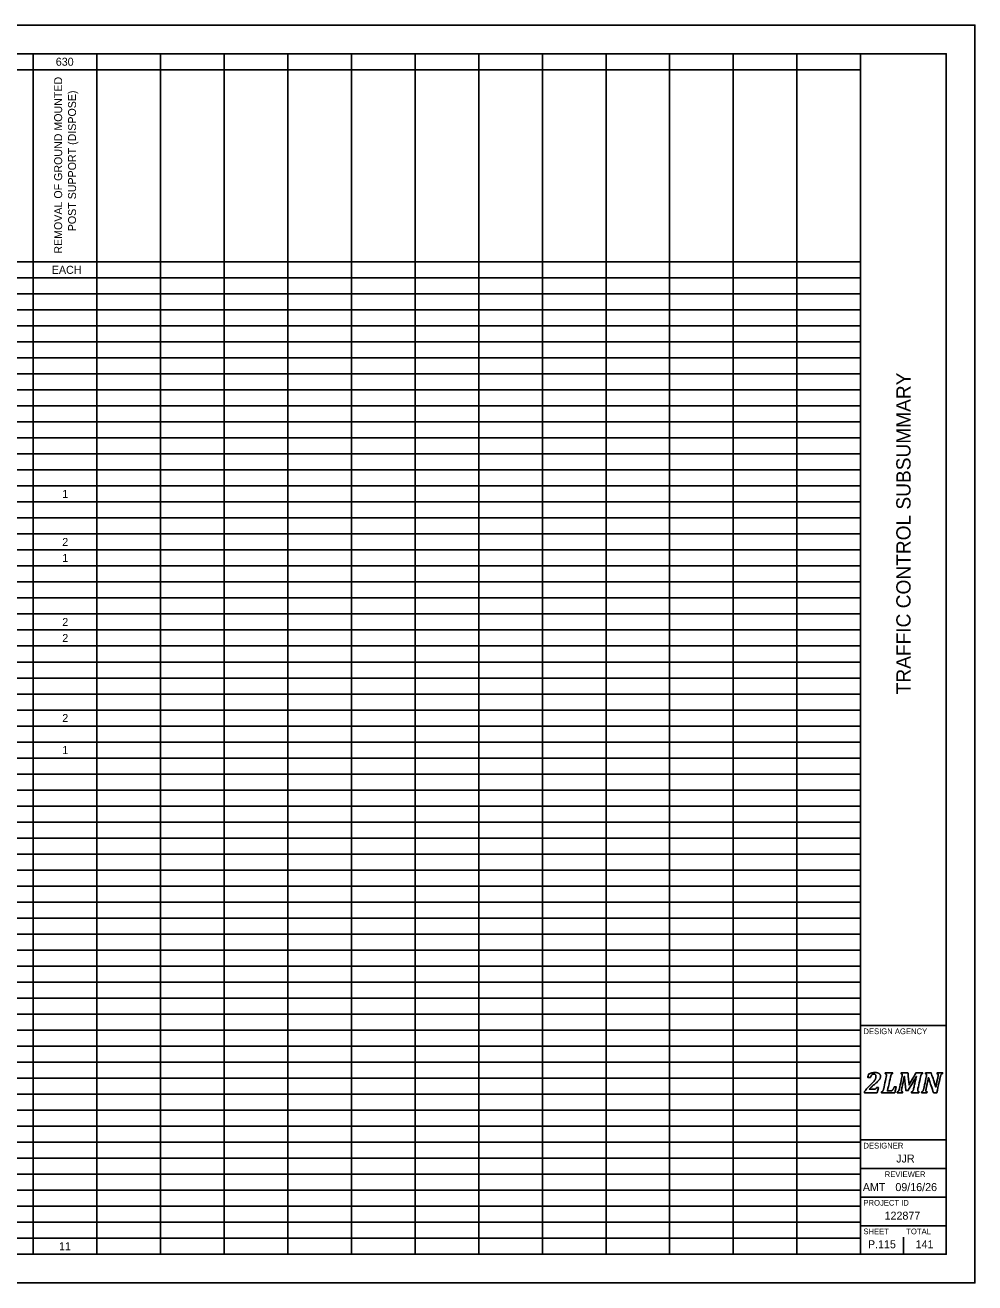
# Model space of a CAD drawing. Extents: x 0 to 34, y 0 to 22.
# Drawn here: x 17.38 to 34, y 0 to 22 of the extents above; entities that cross this region are included whole.
import ezdxf

# ---------------------------------------------------------------- set-up
doc = ezdxf.new("R2010")
doc.units = 0
for name, color, linetype in [('SH_Border', 7, 'Continuous'), ('SH_Cut_Line', 7, 'Continuous'), ('SH_Data', 7, 'Continuous'), ('SH_Text', 7, 'Continuous')]:
    doc.layers.add(name, color=color, linetype=linetype)

msp = doc.modelspace()

# ---------------------------------------------------------------- linework, layer by layer
at = {"layer": 'SH_Border'}
for p, q in [((32, 0.5), (32, 21.5)), ((32, 4.5), (33.5, 4.5)), ((32, 2.5), (33.5, 2.5)), ((32, 2), (33.5, 2)), ((32, 1.5), (33.5, 1.5)), ((32, 1), (33.5, 1))]:
    msp.add_line(p, q, dxfattribs=at)
msp.add_lwpolyline([(1.5, 21.5), (33.5, 21.5), (33.5, 0.5), (1.5, 0.5)], close=True, dxfattribs=at)
at = {"layer": 'SH_Cut_Line'}
msp.add_lwpolyline([(0, 0), (34, 0), (34, 22), (0, 22)], close=True, dxfattribs=at)
at = {"layer": 'SH_Data'}
for p, q in [((32.75, 3.5), (32.75, 3.5)), ((32.375, 0.675), (32.375, 0.675)), ((32.75, 0.5), (32.75, 0.8))]:
    msp.add_line(p, q, dxfattribs=at)
for points in [[(32.237, 3.388), (32.246, 3.388), (32.253, 3.389), (32.258, 3.39), (32.263, 3.392), (32.267, 3.394), (32.27, 3.397), (32.273, 3.401), (32.277, 3.408), (32.281, 3.417), (32.281, 3.417), (32.312, 3.417), (32.312, 3.417), (32.312, 3.417), (32.29, 3.326), (32.29, 3.326), (32.29, 3.326), (32.066, 3.326), (32.066, 3.326), (32.066, 3.326), (32.069, 3.343), (32.069, 3.343), (32.078, 3.358), (32.091, 3.375), (32.106, 3.394), (32.122, 3.412), (32.144, 3.435), (32.172, 3.462), (32.197, 3.486), (32.217, 3.506), (32.23, 3.521), (32.243, 3.537), (32.253, 3.551), (32.259, 3.566), (32.266, 3.58), (32.269, 3.595), (32.269, 3.61), (32.269, 3.622), (32.266, 3.632), (32.26, 3.64), (32.253, 3.647), (32.245, 3.65), (32.234, 3.65), (32.22, 3.65), (32.208, 3.646), (32.198, 3.636), (32.188, 3.627), (32.18, 3.613), (32.172, 3.593), (32.172, 3.593), (32.126, 3.593), (32.126, 3.593), (32.126, 3.593), (32.14, 3.654), (32.14, 3.654), (32.166, 3.663), (32.188, 3.669), (32.205, 3.673), (32.223, 3.676), (32.24, 3.678), (32.258, 3.678), (32.278, 3.678), (32.295, 3.675), (32.309, 3.669), (32.322, 3.664), (32.332, 3.656), (32.339, 3.646), (32.345, 3.637), (32.348, 3.626), (32.348, 3.613), (32.348, 3.602), (32.346, 3.591), (32.342, 3.581), (32.339, 3.571), (32.333, 3.56), (32.324, 3.549), (32.315, 3.539), (32.304, 3.526), (32.289, 3.513), (32.275, 3.499), (32.254, 3.482), (32.228, 3.46), (32.216, 3.45), (32.202, 3.438), (32.188, 3.425), (32.174, 3.412), (32.162, 3.4), (32.154, 3.391), (32.154, 3.391), (32.153, 3.388), (32.153, 3.388), (32.153, 3.388), (32.237, 3.388), (32.237, 3.388)], [(32.237, 3.388), (32.237, 3.388), (32.153, 3.388), (32.153, 3.388), (32.153, 3.388), (32.154, 3.391), (32.154, 3.391), (32.162, 3.4), (32.174, 3.412), (32.188, 3.425), (32.202, 3.438), (32.216, 3.45), (32.228, 3.46), (32.254, 3.482), (32.275, 3.499), (32.289, 3.513), (32.304, 3.526), (32.315, 3.539), (32.324, 3.549), (32.333, 3.56), (32.339, 3.571), (32.342, 3.581), (32.346, 3.591), (32.348, 3.602), (32.348, 3.613), (32.348, 3.626), (32.345, 3.637), (32.339, 3.646), (32.332, 3.656), (32.322, 3.664), (32.309, 3.669), (32.295, 3.675), (32.278, 3.678), (32.258, 3.678), (32.24, 3.678), (32.223, 3.676), (32.205, 3.673), (32.188, 3.669), (32.166, 3.663), (32.14, 3.654), (32.14, 3.654), (32.126, 3.593), (32.126, 3.593), (32.126, 3.593), (32.172, 3.593), (32.172, 3.593), (32.18, 3.613), (32.188, 3.627), (32.198, 3.636), (32.208, 3.646), (32.22, 3.65), (32.234, 3.65), (32.245, 3.65), (32.253, 3.647), (32.26, 3.64), (32.266, 3.632), (32.269, 3.622), (32.269, 3.61), (32.269, 3.595), (32.266, 3.58), (32.259, 3.566), (32.253, 3.551), (32.243, 3.537), (32.23, 3.521), (32.217, 3.506), (32.197, 3.486), (32.172, 3.462), (32.144, 3.435), (32.122, 3.412), (32.106, 3.394), (32.091, 3.375), (32.078, 3.358), (32.069, 3.343), (32.069, 3.343), (32.066, 3.326), (32.066, 3.326), (32.066, 3.326), (32.29, 3.326), (32.29, 3.326), (32.29, 3.326), (32.312, 3.417), (32.312, 3.417), (32.312, 3.417), (32.281, 3.417), (32.281, 3.417), (32.277, 3.408), (32.273, 3.401), (32.27, 3.397), (32.267, 3.394), (32.263, 3.392), (32.258, 3.39), (32.253, 3.389), (32.246, 3.388), (32.237, 3.388)], [(32.518, 3.356), (32.527, 3.356), (32.533, 3.357), (32.538, 3.358), (32.542, 3.36), (32.546, 3.362), (32.55, 3.365), (32.554, 3.368), (32.558, 3.372), (32.562, 3.377), (32.567, 3.382), (32.571, 3.388), (32.576, 3.397), (32.58, 3.405), (32.585, 3.415), (32.589, 3.427), (32.589, 3.427), (32.624, 3.427), (32.624, 3.427), (32.624, 3.427), (32.598, 3.326), (32.598, 3.326), (32.598, 3.326), (32.365, 3.326), (32.365, 3.326), (32.365, 3.326), (32.369, 3.343), (32.369, 3.343), (32.376, 3.345), (32.381, 3.348), (32.385, 3.351), (32.389, 3.355), (32.392, 3.36), (32.395, 3.366), (32.398, 3.373), (32.4, 3.382), (32.403, 3.395), (32.403, 3.395), (32.449, 3.605), (32.449, 3.605), (32.452, 3.615), (32.453, 3.625), (32.453, 3.635), (32.453, 3.642), (32.451, 3.647), (32.448, 3.651), (32.444, 3.654), (32.439, 3.656), (32.432, 3.657), (32.432, 3.657), (32.435, 3.674), (32.435, 3.674), (32.435, 3.674), (32.563, 3.674), (32.563, 3.674), (32.563, 3.674), (32.559, 3.657), (32.559, 3.657), (32.552, 3.655), (32.547, 3.652), (32.543, 3.649), (32.539, 3.645), (32.536, 3.64), (32.533, 3.634), (32.531, 3.627), (32.528, 3.618), (32.525, 3.605), (32.525, 3.605), (32.47, 3.356), (32.47, 3.356), (32.47, 3.356), (32.518, 3.356), (32.518, 3.356)], [(32.518, 3.356), (32.518, 3.356), (32.47, 3.356), (32.47, 3.356), (32.47, 3.356), (32.525, 3.605), (32.525, 3.605), (32.528, 3.618), (32.531, 3.627), (32.533, 3.634), (32.536, 3.64), (32.539, 3.645), (32.543, 3.649), (32.547, 3.652), (32.552, 3.655), (32.559, 3.657), (32.559, 3.657), (32.563, 3.674), (32.563, 3.674), (32.563, 3.674), (32.435, 3.674), (32.435, 3.674), (32.435, 3.674), (32.432, 3.657), (32.432, 3.657), (32.439, 3.656), (32.444, 3.654), (32.448, 3.651), (32.451, 3.647), (32.453, 3.642), (32.453, 3.635), (32.453, 3.625), (32.452, 3.615), (32.449, 3.605), (32.449, 3.605), (32.403, 3.395), (32.403, 3.395), (32.4, 3.382), (32.398, 3.373), (32.395, 3.366), (32.392, 3.36), (32.389, 3.355), (32.385, 3.351), (32.381, 3.348), (32.376, 3.345), (32.369, 3.343), (32.369, 3.343), (32.365, 3.326), (32.365, 3.326), (32.365, 3.326), (32.598, 3.326), (32.598, 3.326), (32.598, 3.326), (32.624, 3.427), (32.624, 3.427), (32.624, 3.427), (32.589, 3.427), (32.589, 3.427), (32.585, 3.415), (32.58, 3.405), (32.576, 3.397), (32.571, 3.388), (32.567, 3.382), (32.562, 3.377), (32.558, 3.372), (32.554, 3.368), (32.55, 3.365), (32.546, 3.362), (32.542, 3.36), (32.538, 3.358), (32.533, 3.357), (32.527, 3.356), (32.518, 3.356)], [(32.829, 3.674), (32.829, 3.674), (32.849, 3.461), (32.849, 3.461), (32.849, 3.461), (32.969, 3.674), (32.969, 3.674), (32.969, 3.674), (33.087, 3.674), (33.087, 3.674), (33.087, 3.674), (33.084, 3.657), (33.084, 3.657), (33.077, 3.655), (33.071, 3.652), (33.067, 3.649), (33.064, 3.645), (33.06, 3.64), (33.058, 3.634), (33.055, 3.627), (33.052, 3.618), (33.05, 3.605), (33.05, 3.605), (33.003, 3.395), (33.003, 3.395), (33.002, 3.39), (33.002, 3.387), (33.001, 3.384), (33.001, 3.382), (33.001, 3.379), (33, 3.376), (33, 3.373), (33, 3.369), (33, 3.365), (33, 3.358), (33.002, 3.353), (33.005, 3.349), (33.008, 3.346), (33.014, 3.344), (33.021, 3.343), (33.021, 3.343), (33.018, 3.326), (33.018, 3.326), (33.018, 3.326), (32.89, 3.326), (32.89, 3.326), (32.89, 3.326), (32.893, 3.343), (32.893, 3.343), (32.9, 3.345), (32.906, 3.348), (32.91, 3.351), (32.914, 3.355), (32.917, 3.36), (32.919, 3.366), (32.922, 3.373), (32.925, 3.382), (32.928, 3.395), (32.928, 3.395), (32.951, 3.502), (32.951, 3.502), (32.954, 3.513), (32.957, 3.529), (32.962, 3.548), (32.967, 3.568), (32.972, 3.588), (32.978, 3.609), (32.978, 3.609), (32.973, 3.609), (32.973, 3.609), (32.965, 3.594), (32.957, 3.579), (32.948, 3.563), (32.948, 3.563), (32.833, 3.364), (32.833, 3.364), (32.833, 3.364), (32.792, 3.364), (32.792, 3.364), (32.792, 3.364), (32.775, 3.518), (32.775, 3.518), (32.773, 3.537), (32.772, 3.554), (32.77, 3.569), (32.769, 3.583), (32.768, 3.597), (32.768, 3.611), (32.768, 3.611), (32.764, 3.611), (32.764, 3.611), (32.761, 3.596), (32.758, 3.578), (32.755, 3.558), (32.751, 3.538), (32.747, 3.521), (32.744, 3.507), (32.744, 3.507), (32.72, 3.395), (32.72, 3.395), (32.719, 3.39), (32.718, 3.387), (32.718, 3.384), (32.717, 3.382), (32.717, 3.379), (32.717, 3.376), (32.717, 3.373), (32.716, 3.369), (32.716, 3.365), (32.716, 3.358), (32.718, 3.353), (32.721, 3.349), (32.725, 3.346), (32.73, 3.344), (32.738, 3.343), (32.738, 3.343), (32.734, 3.326), (32.734, 3.326), (32.734, 3.326), (32.641, 3.326), (32.641, 3.326), (32.641, 3.326), (32.644, 3.343), (32.644, 3.343), (32.651, 3.345), (32.657, 3.348), (32.661, 3.351), (32.665, 3.355), (32.668, 3.36), (32.67, 3.366), (32.673, 3.373), (32.676, 3.382), (32.679, 3.395), (32.679, 3.395), (32.725, 3.605), (32.725, 3.605), (32.727, 3.615), (32.728, 3.625), (32.728, 3.635), (32.728, 3.642), (32.727, 3.647), (32.723, 3.651), (32.72, 3.654), (32.715, 3.656), (32.707, 3.657), (32.707, 3.657), (32.711, 3.674), (32.711, 3.674), (32.711, 3.674), (32.829, 3.674), (32.829, 3.674)], [(32.829, 3.674), (32.829, 3.674), (32.711, 3.674), (32.711, 3.674), (32.711, 3.674), (32.707, 3.657), (32.707, 3.657), (32.715, 3.656), (32.72, 3.654), (32.723, 3.651), (32.727, 3.647), (32.728, 3.642), (32.728, 3.635), (32.728, 3.625), (32.727, 3.615), (32.725, 3.605), (32.725, 3.605), (32.679, 3.395), (32.679, 3.395), (32.676, 3.382), (32.673, 3.373), (32.67, 3.366), (32.668, 3.36), (32.665, 3.355), (32.661, 3.351), (32.657, 3.348), (32.651, 3.345), (32.644, 3.343), (32.644, 3.343), (32.641, 3.326), (32.641, 3.326), (32.641, 3.326), (32.734, 3.326), (32.734, 3.326), (32.734, 3.326), (32.738, 3.343), (32.738, 3.343), (32.73, 3.344), (32.725, 3.346), (32.721, 3.349), (32.718, 3.353), (32.716, 3.358), (32.716, 3.365), (32.716, 3.369), (32.717, 3.373), (32.717, 3.376), (32.717, 3.379), (32.717, 3.382), (32.718, 3.384), (32.718, 3.387), (32.719, 3.39), (32.72, 3.395), (32.72, 3.395), (32.744, 3.507), (32.744, 3.507), (32.747, 3.521), (32.751, 3.538), (32.755, 3.558), (32.758, 3.578), (32.761, 3.596), (32.764, 3.611), (32.764, 3.611), (32.768, 3.611), (32.768, 3.611), (32.768, 3.597), (32.769, 3.583), (32.77, 3.569), (32.772, 3.554), (32.773, 3.537), (32.775, 3.518), (32.775, 3.518), (32.792, 3.364), (32.792, 3.364), (32.792, 3.364), (32.833, 3.364), (32.833, 3.364), (32.833, 3.364), (32.948, 3.563), (32.948, 3.563), (32.957, 3.579), (32.965, 3.594), (32.973, 3.609), (32.973, 3.609), (32.978, 3.609), (32.978, 3.609), (32.972, 3.588), (32.967, 3.568), (32.962, 3.548), (32.957, 3.529), (32.954, 3.513), (32.951, 3.502), (32.951, 3.502), (32.928, 3.395), (32.928, 3.395), (32.925, 3.382), (32.922, 3.373), (32.919, 3.366), (32.917, 3.36), (32.914, 3.355), (32.91, 3.351), (32.906, 3.348), (32.9, 3.345), (32.893, 3.343), (32.893, 3.343), (32.89, 3.326), (32.89, 3.326), (32.89, 3.326), (33.018, 3.326), (33.018, 3.326), (33.018, 3.326), (33.021, 3.343), (33.021, 3.343), (33.014, 3.344), (33.008, 3.346), (33.005, 3.349), (33.002, 3.353), (33, 3.358), (33, 3.365), (33, 3.369), (33, 3.373), (33, 3.376), (33.001, 3.379), (33.001, 3.382), (33.001, 3.384), (33.002, 3.387), (33.002, 3.39), (33.003, 3.395), (33.003, 3.395), (33.05, 3.605), (33.05, 3.605), (33.052, 3.618), (33.055, 3.627), (33.058, 3.634), (33.06, 3.64), (33.064, 3.645), (33.067, 3.649), (33.071, 3.652), (33.077, 3.655), (33.084, 3.657), (33.084, 3.657), (33.087, 3.674), (33.087, 3.674), (33.087, 3.674), (32.969, 3.674), (32.969, 3.674), (32.969, 3.674), (32.849, 3.461), (32.849, 3.461), (32.849, 3.461), (32.829, 3.674), (32.829, 3.674)], [(33.137, 3.674), (33.137, 3.674), (33.234, 3.674), (33.234, 3.674), (33.234, 3.674), (33.283, 3.53), (33.283, 3.53), (33.296, 3.49), (33.307, 3.456), (33.315, 3.426), (33.315, 3.426), (33.318, 3.426), (33.318, 3.426), (33.323, 3.455), (33.329, 3.488), (33.337, 3.523), (33.337, 3.523), (33.355, 3.605), (33.355, 3.605), (33.357, 3.615), (33.358, 3.625), (33.358, 3.635), (33.358, 3.642), (33.357, 3.647), (33.353, 3.651), (33.35, 3.654), (33.345, 3.656), (33.337, 3.657), (33.337, 3.657), (33.341, 3.674), (33.341, 3.674), (33.341, 3.674), (33.434, 3.674), (33.434, 3.674), (33.434, 3.674), (33.431, 3.657), (33.431, 3.657), (33.424, 3.655), (33.418, 3.652), (33.414, 3.649), (33.41, 3.645), (33.407, 3.64), (33.405, 3.634), (33.402, 3.627), (33.399, 3.618), (33.396, 3.605), (33.396, 3.605), (33.335, 3.326), (33.335, 3.326), (33.335, 3.326), (33.277, 3.326), (33.277, 3.326), (33.277, 3.326), (33.216, 3.504), (33.216, 3.504), (33.211, 3.518), (33.207, 3.531), (33.204, 3.543), (33.2, 3.556), (33.195, 3.571), (33.19, 3.59), (33.19, 3.59), (33.186, 3.59), (33.186, 3.59), (33.185, 3.579), (33.182, 3.563), (33.179, 3.543), (33.175, 3.523), (33.17, 3.501), (33.165, 3.478), (33.165, 3.478), (33.147, 3.395), (33.147, 3.395), (33.146, 3.39), (33.145, 3.387), (33.145, 3.384), (33.144, 3.382), (33.144, 3.379), (33.144, 3.376), (33.143, 3.373), (33.143, 3.369), (33.143, 3.365), (33.143, 3.358), (33.145, 3.353), (33.148, 3.349), (33.152, 3.346), (33.157, 3.344), (33.164, 3.343), (33.164, 3.343), (33.161, 3.326), (33.161, 3.326), (33.161, 3.326), (33.067, 3.326), (33.067, 3.326), (33.067, 3.326), (33.071, 3.343), (33.071, 3.343), (33.078, 3.345), (33.083, 3.348), (33.087, 3.351), (33.091, 3.355), (33.094, 3.36), (33.097, 3.366), (33.1, 3.373), (33.102, 3.382), (33.105, 3.395), (33.105, 3.395), (33.151, 3.605), (33.151, 3.605), (33.154, 3.615), (33.155, 3.625), (33.155, 3.635), (33.155, 3.642), (33.153, 3.647), (33.15, 3.651), (33.146, 3.654), (33.141, 3.656), (33.134, 3.657), (33.134, 3.657), (33.137, 3.674), (33.137, 3.674)], [(33.137, 3.674), (33.137, 3.674), (33.134, 3.657), (33.134, 3.657), (33.141, 3.656), (33.146, 3.654), (33.15, 3.651), (33.153, 3.647), (33.155, 3.642), (33.155, 3.635), (33.155, 3.625), (33.154, 3.615), (33.151, 3.605), (33.151, 3.605), (33.105, 3.395), (33.105, 3.395), (33.102, 3.382), (33.1, 3.373), (33.097, 3.366), (33.094, 3.36), (33.091, 3.355), (33.087, 3.351), (33.083, 3.348), (33.078, 3.345), (33.071, 3.343), (33.071, 3.343), (33.067, 3.326), (33.067, 3.326), (33.067, 3.326), (33.161, 3.326), (33.161, 3.326), (33.161, 3.326), (33.164, 3.343), (33.164, 3.343), (33.157, 3.344), (33.152, 3.346), (33.148, 3.349), (33.145, 3.353), (33.143, 3.358), (33.143, 3.365), (33.143, 3.369), (33.143, 3.373), (33.144, 3.376), (33.144, 3.379), (33.144, 3.382), (33.145, 3.384), (33.145, 3.387), (33.146, 3.39), (33.147, 3.395), (33.147, 3.395), (33.165, 3.478), (33.165, 3.478), (33.17, 3.501), (33.175, 3.523), (33.179, 3.543), (33.182, 3.563), (33.185, 3.579), (33.186, 3.59), (33.186, 3.59), (33.19, 3.59), (33.19, 3.59), (33.195, 3.571), (33.2, 3.556), (33.204, 3.543), (33.207, 3.531), (33.211, 3.518), (33.216, 3.504), (33.216, 3.504), (33.277, 3.326), (33.277, 3.326), (33.277, 3.326), (33.335, 3.326), (33.335, 3.326), (33.335, 3.326), (33.396, 3.605), (33.396, 3.605), (33.399, 3.618), (33.402, 3.627), (33.405, 3.634), (33.407, 3.64), (33.41, 3.645), (33.414, 3.649), (33.418, 3.652), (33.424, 3.655), (33.431, 3.657), (33.431, 3.657), (33.434, 3.674), (33.434, 3.674), (33.434, 3.674), (33.341, 3.674), (33.341, 3.674), (33.341, 3.674), (33.337, 3.657), (33.337, 3.657), (33.345, 3.656), (33.35, 3.654), (33.353, 3.651), (33.357, 3.647), (33.358, 3.642), (33.358, 3.635), (33.358, 3.625), (33.357, 3.615), (33.355, 3.605), (33.355, 3.605), (33.337, 3.523), (33.337, 3.523), (33.329, 3.488), (33.323, 3.455), (33.318, 3.426), (33.318, 3.426), (33.315, 3.426), (33.315, 3.426), (33.307, 3.456), (33.296, 3.49), (33.283, 3.53), (33.283, 3.53), (33.234, 3.674), (33.234, 3.674), (33.234, 3.674), (33.137, 3.674), (33.137, 3.674)]]:
    msp.add_open_spline(points, degree=3, dxfattribs=at)
at = {"layer": 'SH_Text'}
for p, q in [((1.5, 21.5), (32, 21.5)), ((17.52, 21.5), (17.52, 0.5)), ((18.634, 21.5), (18.634, 0.5)), ((19.748, 21.5), (19.748, 0.5)), ((20.861, 21.5), (20.861, 0.5)), ((21.975, 21.5), (21.975, 0.5)), ((23.089, 21.5), (23.089, 0.5)), ((24.203, 21.5), (24.203, 0.5)), ((25.317, 21.5), (25.317, 0.5)), ((26.431, 21.5), (26.431, 0.5)), ((27.545, 21.5), (27.545, 0.5)), ((28.658, 21.5), (28.658, 0.5)), ((29.772, 21.5), (29.772, 0.5)), ((30.886, 21.5), (30.886, 0.5)), ((32, 21.5), (32, 0.5)), ((10.673, 21.22), (32, 21.22)), ((10.673, 17.86), (32, 17.86)), ((1.5, 17.58), (32, 17.58)), ((1.5, 17.3), (32, 17.3)), ((1.5, 17.02), (32, 17.02)), ((1.5, 16.74), (32, 16.74)), ((1.5, 16.46), (32, 16.46)), ((1.5, 16.18), (32, 16.18)), ((1.5, 15.9), (32, 15.9)), ((1.5, 15.62), (32, 15.62)), ((1.5, 15.34), (32, 15.34)), ((1.5, 15.06), (32, 15.06)), ((1.5, 14.78), (32, 14.78)), ((1.5, 14.5), (32, 14.5)), ((1.5, 14.22), (32, 14.22)), ((1.5, 13.94), (32, 13.94)), ((1.5, 13.66), (32, 13.66)), ((1.5, 13.38), (32, 13.38)), ((1.5, 13.1), (32, 13.1)), ((1.5, 12.82), (32, 12.82)), ((1.5, 12.54), (32, 12.54)), ((1.5, 12.26), (32, 12.26)), ((1.5, 11.98), (32, 11.98)), ((1.5, 11.7), (32, 11.7)), ((1.5, 11.42), (32, 11.42)), ((1.5, 11.14), (32, 11.14)), ((1.5, 10.86), (32, 10.86)), ((1.5, 10.58), (32, 10.58)), ((1.5, 10.3), (32, 10.3)), ((1.5, 10.02), (32, 10.02)), ((1.5, 9.74), (32, 9.74)), ((1.5, 9.46), (32, 9.46)), ((1.5, 9.18), (32, 9.18)), ((1.5, 8.9), (32, 8.9)), ((1.5, 8.62), (32, 8.62)), ((1.5, 8.34), (32, 8.34)), ((1.5, 8.06), (32, 8.06)), ((1.5, 7.78), (32, 7.78)), ((1.5, 7.5), (32, 7.5)), ((1.5, 7.22), (32, 7.22)), ((1.5, 6.94), (32, 6.94)), ((1.5, 6.66), (32, 6.66)), ((1.5, 6.38), (32, 6.38)), ((1.5, 6.1), (32, 6.1)), ((1.5, 5.82), (32, 5.82)), ((1.5, 5.54), (32, 5.54)), ((1.5, 5.26), (32, 5.26)), ((1.5, 4.98), (32, 4.98)), ((1.5, 4.7), (32, 4.7)), ((1.5, 4.42), (32, 4.42)), ((1.5, 4.14), (32, 4.14)), ((1.5, 3.86), (32, 3.86)), ((1.5, 3.58), (32, 3.58)), ((1.5, 3.3), (32, 3.3)), ((1.5, 3.02), (32, 3.02)), ((1.5, 2.74), (32, 2.74)), ((1.5, 2.46), (32, 2.46)), ((1.5, 2.18), (32, 2.18)), ((1.5, 1.9), (32, 1.9)), ((1.5, 1.62), (32, 1.62)), ((1.5, 1.34), (32, 1.34)), ((1.5, 1.06), (32, 1.06)), ((1.5, 0.78), (32, 0.78)), ((1.5, 0.5), (32, 0.5))]:
    msp.add_line(p, q, dxfattribs=at)

# ---------------------------------------------------------------- texts
at = {"layer": 'SH_Data'}
msp.add_text('TRAFFIC CONTROL SUBSUMMARY', height=0.25, rotation=90, dxfattribs=at).set_placement((32.875, 10.295))
for s, height, p in [('DESIGN AGENCY', 0.1, (32.05, 4.35)), ('DESIGNER', 0.1, (32.05, 2.35)), ('JJR', 0.14, (32.624, 2.105)), ('REVIEWER', 0.1, (32.422, 1.85)), ('AMT', 0.14, (32.039, 1.605)), ('09/16/26', 0.14, (32.609, 1.605)), ('PROJECT ID', 0.1, (32.05, 1.35)), ('122877', 0.14, (32.42, 1.105)), ('SHEET', 0.1, (32.05, 0.85)), ('TOTAL', 0.1, (32.8, 0.85)), ('P.115', 0.14, (32.129, 0.605)), ('141', 0.14, (32.963, 0.605))]:
    msp.add_text(s, height=height, dxfattribs=at).set_placement(p)
at = {"layer": 'SH_Text'}
for s, p in [('630', (17.914, 21.29)), ('EACH', (17.844, 17.65)), ('1', (18.027, 13.73)), ('2', (18.027, 12.89)), ('1', (18.027, 12.61)), ('2', (18.027, 11.49)), ('2', (18.027, 11.21)), ('2', (18.027, 9.81)), ('1', (18.027, 9.25)), ('11', (17.971, 0.57))]:
    msp.add_text(s, height=0.14, dxfattribs=at).set_placement(p)
for s, p in [('REMOVAL OF GROUND MOUNTED ', (18.025, 18.003)), ('POST SUPPORT (DISPOSE)', (18.268, 18.395))]:
    msp.add_text(s, height=0.13923, rotation=90, dxfattribs=at).set_placement(p)

doc.saveas('drawing.dxf')
